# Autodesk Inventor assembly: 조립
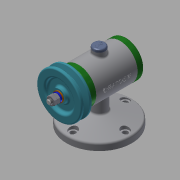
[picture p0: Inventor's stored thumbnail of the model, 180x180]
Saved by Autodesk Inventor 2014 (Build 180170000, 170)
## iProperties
Created: 2018-12
Part Number: 조립
Document SubType Name: Assembly
Designer: kh
Author: kh
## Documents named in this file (15)
- C:\Users\kh\Desktop\481207V1014\조립.iam
- C:\Users\kh\Desktop\481207V1014\본체.ipt
- C:\Users\kh\Desktop\481207V1014\V벨트풀리.ipt
- C:\Users\kh\Desktop\481207V1014\고무캡.ipt
- C:\Users\kh\Desktop\481207V1014\너트 M8.ipt
- 너트 M8.ipt
- C:\Users\kh\Desktop\481207V1014\뒤커버.ipt
- C:\Users\kh\Desktop\481207V1014\베어링 15 x 32 x 9.ipt
- C:\Users\kh\Desktop\481207V1014\볼트 M4 x 12.ipt
- C:\Users\kh\Desktop\481207V1014\스프링와셔 8.ipt
- C:\Users\kh\Desktop\481207V1014\앞커버.ipt
- C:\Users\kh\Desktop\481207V1014\오일 실 15 25 7.ipt
- C:\Users\kh\Desktop\481207V1014\와셔 8x17.ipt
- C:\Users\kh\Desktop\481207V1014\축.ipt
- C:\Users\kh\Desktop\481207V1014\키 3 x 3 x 12.ipt
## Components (2 placed, 2 different names)
1. V벨트풀리:1 — Insert:14, Mate:1, Insert:15
2. 고무캡:1 — Insert:13, Angle:3
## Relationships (5: Insert 3, Angle 1, Mate 1)
- Insert:13: 고무캡:1
- Angle:3: 고무캡:1
- Insert:14: V벨트풀리:1
- Mate:1: V벨트풀리:1
- Insert:15: V벨트풀리:1
